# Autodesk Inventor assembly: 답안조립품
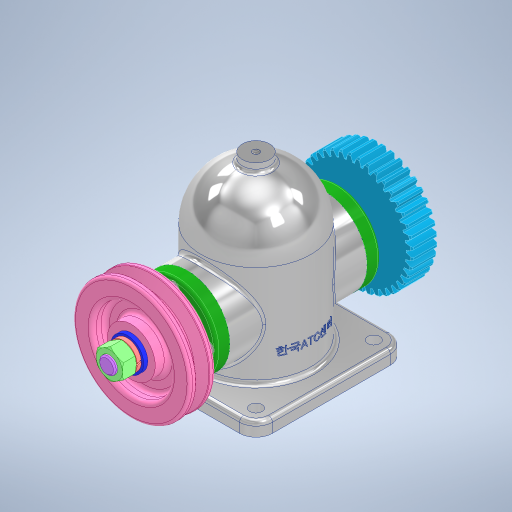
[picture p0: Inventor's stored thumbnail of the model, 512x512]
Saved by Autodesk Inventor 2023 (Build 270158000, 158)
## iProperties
Created: 2025-04
Part Number: 답안조립품
Document SubType Name: Assembly
Designer: User
Author: User
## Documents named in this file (14)
- C:\Users\User\Desktop\750406V1012\답안조립품.iam
- C:\Users\User\Desktop\750406V1012\본체.ipt
- C:\Users\User\Desktop\750406V1012\공용부품_2025.04.09\깊은 홈 볼 베어링 6203.ipt
- C:\Users\User\Desktop\750406V1012\공용부품_2025.04.09\축.ipt
- C:\Users\User\Desktop\750406V1012\공용부품_2025.04.09\커버.ipt
- C:\Users\User\Desktop\750406V1012\공용부품_2025.04.09\오일 실 26 38 8.ipt
- C:\Users\User\Desktop\750406V1012\공용부품_2025.04.09\6각 구멍붙이 볼트 M4x12.ipt
- C:\Users\User\Desktop\750406V1012\공용부품_2025.04.09\칼라.ipt
- C:\Users\User\Desktop\750406V1012\공용부품_2025.04.09\평행 키 5x5x12.ipt
- C:\Users\User\Desktop\750406V1012\공용부품_2025.04.09\스퍼기어.ipt
- C:\Users\User\Desktop\750406V1012\공용부품_2025.04.09\V 벨트 풀리.ipt
- C:\Users\User\Desktop\750406V1012\공용부품_2025.04.09\평와셔 M12.ipt
- C:\Users\User\Desktop\750406V1012\공용부품_2025.04.09\스프링 와셔 M12.ipt
- C:\Users\User\Desktop\750406V1012\공용부품_2025.04.09\6각 너트 M12x1.ipt
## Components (11 placed, 3 different names)
1. 6각 구멍붙이 볼트 M4x12:1
2. 6각 구멍붙이 볼트 M4x12:2
3. 6각 구멍붙이 볼트 M4x12:3
4. 6각 구멍붙이 볼트 M4x12:4
5. 6각 구멍붙이 볼트 M4x12:5
6. 6각 구멍붙이 볼트 M4x12:6
7. 6각 구멍붙이 볼트 M4x12:7
8. 6각 구멍붙이 볼트 M4x12:8
9. V 벨트 풀리:1
10. 6각 너트 M12x1:1
11. 6각 너트 M12x1:2
